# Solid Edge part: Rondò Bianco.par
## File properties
Title: RONDO' BIANCO
Author: DESYS
Template: Iso Part.par
Last saved by: i.fialdini
Revision: 52
Application: Solid Edge
Tipo di contenuto documento: 0
Accuracy: 0.990
Document Number: 8008
Revision: 0
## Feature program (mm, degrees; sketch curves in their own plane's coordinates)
sketch for "unnamed RevolvedProtrusion 1" plane through (6.3942, 0, 6.3942) normal (0, -1, 0) x-axis (1, 0, 0)
revolve "unnamed RevolvedProtrusion 1" add full turn 360 deg about sketch line (-6.3942, -6.3942) -> (-6.3942, 166.6058)
sketch for "unnamed RevolvedCutout 1" plane through (0, 0, 0) normal (1, 0, 0) x-axis (0, 1, 0)
  arc centre (20.9379, 324.2432) radius 290 from (-226.5, 173) to (0, 35) ccw
  line (0, 224.6777) -> (-226.5, 224.6777)
  line (-226.5, 173) -> (-226.5, 224.6777)
  dimension (linear) = 226.5
revolve "unnamed RevolvedCutout 1" cut full turn 360 deg about sketch line (0, 35) -> (0, 224.6777)
sketch for "ProtrusioneEstrusa_1" plane through (0.0178, 0, 163) normal (0, 0, 1) x-axis (-1, 0, 0)
  arc centre (0.0201, -328.3724) radius 210.8724 from (-146.0797, -176.3131) to (146.1166, -176.31) cw
extrude "ProtrusioneEstrusa_1" add through along -normal  Profile_Plane1_Distance = 10 mm
sketch for "unnamed Cutout 1" plane through (0.0178, 0, 0) normal (0, 0, -1) x-axis (1, 0, 0)
extrude "unnamed Cutout 1" cut finite 20 along -normal
sketch for "ProtrusioneEstrusa_2" plane through (0, 0, 20) normal (0, 0, -1) x-axis (1, 0, 0)
extrude "ProtrusioneEstrusa_2" add finite 20 along +normal
sketch for "unnamed Cutout 2" plane through (0, 0, 0) normal (0, 0, -1) x-axis (1, 0, 0)
extrude "unnamed Cutout 2" cut finite 455 along -normal
sketch for "ProtrusioneEstrusa_3" plane through (0, 0, 20) normal (0, 0, -1) x-axis (-1, 0, 0)
extrude "ProtrusioneEstrusa_3" add finite 20 along -normal
sketch for "ProtrusioneEstrusa_4" plane through (0, 0, 20) normal (0, 0, -1) x-axis (-1, 0, 0)
extrude "ProtrusioneEstrusa_4" add finite 15 along +normal
sketch for "ProtrusioneEstrusa_5" plane through (0, 0.7667, 20) normal (0, 0, -1) x-axis (0, -1, 0)
extrude "ProtrusioneEstrusa_5" add finite 15 along +normal
sketch for "ScavoRivoluzione_2" plane through (0, 0, 0) normal (1, 0, 0) x-axis (0, 1, 0)
revolve "ScavoRivoluzione_2" cut finite 35 deg
sketch for "unnamed Cutout 3" plane through (0, 176.4888, 158) normal (0, 0, -1) x-axis (0.300706, -0.953717, 0)
extrude "unnamed Cutout 3" cut through along +normal
draft "Spoglia_4"  Angles1 = 10 deg
draft "Spoglia_5"  Angles1 = 6 deg
draft "Spoglia_6"  Angles1 = 6 deg
fillet "Rotondo_1" radius 10
fillet "Rotondo_2" radius 3
sketch for "unnamed Cutout 4" plane through (0.0212, 171.5851, 163) normal (0, 0, 1) x-axis (0, -1, 0)
extrude "unnamed Cutout 4" cut through along -normal
fillet "Rotondo_3" radius 10
fillet "Rotondo_4" radius 3
fillet "Rotondo_5" radius 3
sketch for "Foro_2" plane through (0, 0, 0) normal (0, -0.707107, -0.707107) x-axis (1, 0, 0)
  hole centre (0, 223.8029) bore radius 10
hole "Foro_2" diameter 20 finite
fillet "unnamed Round 1"
fillet "Rotondo_9" radius 10
swept cutout "ScavoScorrimento_8"
fillet "Rotondo_8" radius 5
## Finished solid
Body 1: solid body, 77 faces, 158 edges, 84 vertices.
  Faces by surface: blend 27, plane 15, torus 14, cylinder 13, sphere 4, cone 2, spline 2
  Edges by curve: circle 66, intersection 62, line 26, ellipse 4
Bounding box of the edges (mm; curved faces can reach further): 482.270 x 482.320 x 173.000, from (-241.1348, -240.2792, 0) to (241.1348, 242.0404, 173).
Cylindrical faces by radius (mm): R3 x2, R10 x5, R22.5 x1, R30 x1, R30.3234 x1, R95 x1, R140.0112 x1, R210.8724 x1
Conical faces (half-angle, radius in mm at the cone's reference point): 5.0324 deg R242.5 x1, 10 deg R217.5 x1
Toroidal faces (ring radius, tube radius in mm): R-20.9379 r290 x1, R20.8284 r3 x1, R21 r3 x1, R25.5 r3 x2, R27 r3 x1, R51.2966 r180 x1, R98 r3 x1, R137.0112 r3 x1, R200.8724 r10 x1, R214.7006 r10 x1, R214.9827 r3 x1, R229.6192 r10 x1, R232.9209 r5 x1
Spherical faces by radius (mm): R3 x4
Planar faces by outward normal: +x 2, +z 1, -x 2, -z 7, oblique 3
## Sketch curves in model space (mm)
line (282.5, 0, 163) -> (282.5, 0, 213)
line (202.5, 0, 213) -> (282.5, 0, 213)
line (202.5, 0, 213) -> (202.5, 0, 163)
line (202.5, 0, 163) -> (282.5, 0, 163)
line (-202.5, 0, 213) -> (-282.5, 0, 213)
line (-202.5, 0, 213) -> (-202.5, 0, 163)
line (-282.5, 0, 163) -> (-202.5, 0, 163)
line (-282.5, 0, 163) -> (-282.5, 0, 213)
line (0, 282.5, 173) -> (0, 282.5, 223)
line (0, 282.5, 223) -> (0, 202.5, 223)
line (0, 202.5, 223) -> (0, 202.5, 173)
line (0, 202.5, 173) -> (0, 282.5, 173)
line (0, -202.5, 203) -> (0, -202.5, 153)
line (0, -202.5, 203) -> (0, -282.5, 203)
line (0, -282.5, 153) -> (0, -282.5, 203)
line (0, -282.5, 153) -> (0, -202.5, 153)
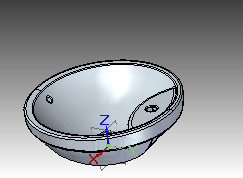
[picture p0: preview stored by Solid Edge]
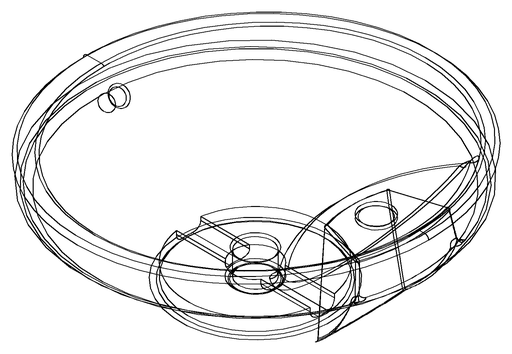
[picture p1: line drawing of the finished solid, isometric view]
